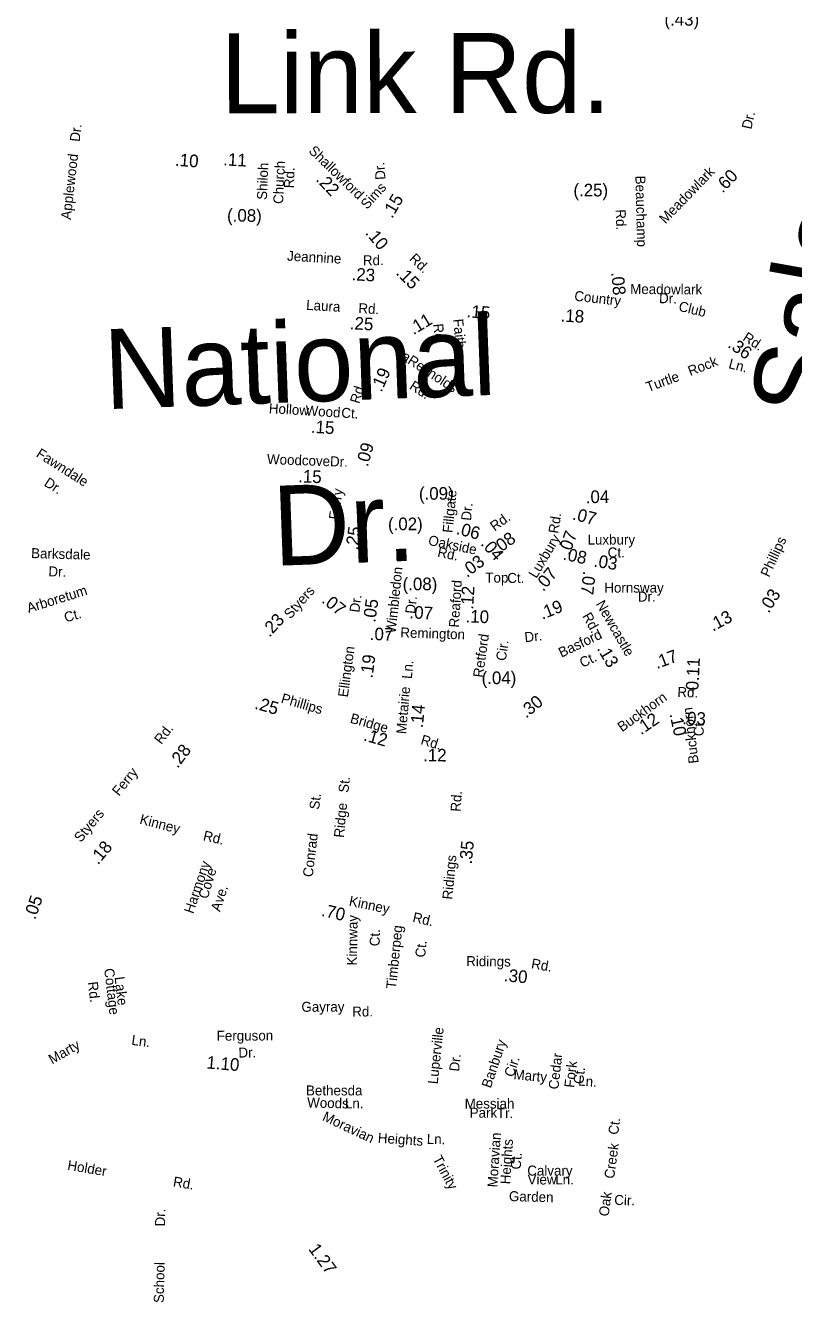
# Model space of a CAD drawing. Extents: x 1553981 to 1780076, y 812965 to 996873.
# Drawn here: x 1628137 to 1629049, y 846914 to 848432 of the extents above; entities that cross this region are included whole.
import ezdxf

# ---------------------------------------------------------------- set-up
doc = ezdxf.new("R2010")
doc.units = 0
for name, color, linetype in [('Exist Road Non-System Type 51 Label', 7, 'Continuous'), ('Exist Road Secondary Mileage Hundredths English Label', 7, 'Continuous'), ('Map Preparation Border Antique Large Shape', 7, 'Continuous')]:
    doc.layers.add(name, color=color, linetype=linetype)

msp = doc.modelspace()

# ---------------------------------------------------------------- texts
at = {"layer": 'Exist Road Non-System Type 51 Label'}
for s, height, rotation, p in [('Link', 95, 0.1507, (1628368.2, 848327.7)), ('Rd.', 95, 359.9684, (1628634.9, 848328.3)), ('Dr.', 11.88, 83.5506, (1628200.8, 848293.5)), ('Salem', 95, 79.854, (1629090.3, 847960.8)), ('Applewood', 11.88, 83.5506, (1628190.3, 848200.9)), ('National', 95, 2.1154, (1628231.3, 847975.9)), ('Rd.', 11.88, 275.4684, (1628621, 848077.2)), ('Faith', 11.88, 275.4684, (1628644.8, 848082.9)), ('La', 11.87, 327.0099, (1628574.9, 848040.7)), ('Reynolds', 11.87, 327.0099, (1628589.7, 848031.1)), ('Rock', 11.88, 21.3244, (1628926.7, 848015.2)), ('Ln.', 11.88, 345.6382, (1628971.5, 848024.9)), ('Rd.', 11.87, 327.0099, (1628591.9, 848000.8)), ('Turtle', 11.88, 19.9111, (1628876.6, 847996.3)), ('Fawndale', 11.88, 327.643, (1628148.2, 847920.2)), ('Dr.', 11.88, 327.643, (1628157.6, 847885.6)), ('Dr.', 95, 2.1154, (1628432, 847789.7)), ('Barksdale', 11.88, 358.3721, (1628143, 847799)), ('Dr.', 11.88, 358.4032, (1628163.6, 847777.3)), ('Arboretum', 11.87, 17.3636, (1628140.2, 847733.6)), ('Ct.', 11.88, 16.4615, (1628184.4, 847722.3)), ('Basford', 11.88, 25.6621, (1628773.6, 847680.4)), ('Ct.', 11.88, 25.6621, (1628798.6, 847668.4)), ('St.', 11.88, 84.1973, (1628520.2, 847519.5)), ('St.', 11.88, 83.0766, (1628485.5, 847499.5)), ('Ridge', 11.88, 84.1973, (1628514.8, 847466.1)), ('Conrad', 11.88, 83.0766, (1628477.8, 847419.2)), ('Harmony', 11.88, 71.4085, (1628335.8, 847375.4)), ('Cove', 11.88, 73.029, (1628352.9, 847392.9)), ('Ave.', 11.88, 71.7839, (1628367.6, 847377.8)), ('Kinnway', 11.88, 89.2551, (1628530.5, 847314.5)), ('Ct.', 11.88, 89.2551, (1628557.5, 847337.4)), ('Timberpeg', 11.88, 84.0792, (1628576.9, 847286.3)), ('Ct.', 11.88, 84.0792, (1628611.4, 847323.6)), ('Cottage', 11.88, 276.7917, (1628229.9, 847310.6)), ('Rd.', 11.88, 276.7917, (1628210.5, 847294.7)), ('Lake', 11.88, 276.7917, (1628242.3, 847300.7)), ('Gayray', 11.87, 0.2324, (1628464.5, 847259.5)), ('Rd.', 11.87, 0.2324, (1628524.9, 847253.9)), ('Ferguson', 11.88, 0.2987, (1628363.8, 847225.1)), ('Luperville', 11.87, 83.8524, (1628626.4, 847173.1)), ('Banbury', 11.88, 71.5075, (1628689.5, 847168)), ('Dr.', 11.88, 0.2944, (1628389.6, 847205.1)), ('Dr.', 11.87, 83.8524, (1628651.8, 847188.1)), ('Cir.', 11.88, 71.5075, (1628716.4, 847181)), ('Cedar', 11.88, 83.6288, (1628769.9, 847166.8)), ('Fork', 11.88, 83.6288, (1628788.7, 847168.8)), ('Ct.', 11.88, 83.6288, (1628799.5, 847173.1)), ('Bethesda', 11.88, 0.0147, (1628469.9, 847160.1)), ('Woods', 11.88, 358.6039, (1628471.2, 847145.8)), ('Ln.', 11.88, 0.3375, (1628516.2, 847144.7)), ('Moravian', 11.88, 334.7401, (1628488.4, 847130.9)), ('Ct.', 11.88, 82.1503, (1628840.8, 847112.8)), ('Heights', 11.88, 355.931, (1628555, 847103.9)), ('Ln.', 11.88, 358.9243, (1628613.4, 847102.5)), ('Moravian', 11.87, 86.2736, (1628697.4, 847050.5)), ('Heights', 11.87, 86.2736, (1628712.5, 847054.2)), ('Creek', 11.87, 82.1505, (1628836.1, 847060.6)), ('Trinity', 11.87, 298.3383, (1628620.1, 847084.8)), ('Ct.', 11.87, 86.2736, (1628725.1, 847071.7)), ('Garden', 11.88, 358.4068, (1628711, 847034.5)), ('Oak', 11.88, 82.5022, (1628829.6, 847015.8)), ('Cir.', 11.88, 358.4067, (1628836.2, 847030)), ('Dr.', 11.88, 89.1855, (1628302.3, 847004.3)), ('School', 11.88, 88.6092, (1628300.8, 846913.2))]:
    msp.add_text(s, height=height, rotation=rotation, dxfattribs=at).set_placement(p)
for s, p in [('Messiah', (1628658.5, 847144.5)), ('Park', (1628664.5, 847133.6)), ('Tr.', (1628696.9, 847133.1)), ('View', (1628733.3, 847054.2)), ('Calvary', (1628732.9, 847064.8)), ('Ln.', (1628766.2, 847054.2))]:
    msp.add_text(s, height=11.88, dxfattribs=at).set_placement(p)
at = {"layer": 'Exist Road Secondary Mileage Hundredths English Label'}
for s, rotation, p in [('(.43)', 359.8869, (1628896, 848432)), ('.11', 356.7836, (1628371.2, 848265.9)), ('.10', 355.4499, (1628313.8, 848265.5)), ('.22', 313.3313, (1628480.9, 848248.3)), ('.60', 46.2244, (1628965.1, 848232.2)), ('(.25)', 0.1572, (1628787.8, 848228.9)), ('.15', 59.7909, (1628572.3, 848202)), ('(.08)', 358.8738, (1628376, 848199.3)), ('.10', 310.3628, (1628539.6, 848185.1)), ('.23', 356.815, (1628523.8, 848129.3)), ('.15', 315.0435, (1628576.1, 848137)), ('.08', 275.1023, (1628832.7, 848138.6)), ('.15', 354.7302, (1628660.4, 848085.4)), ('.25', 356.6887, (1628521.7, 848071.1)), ('.11', 31.2732, (1628597.6, 848063.8)), ('.18', 356.8257, (1628772.3, 848080.2)), ('.36', 324.9959, (1628970.3, 848050.4)), ('.19', 66.2532, (1628559.7, 847995.4)), ('.15', 356.458, (1628475.4, 847948)), ('.09', 74.3042, (1628543.3, 847906.8)), ('.15', 357.9513, (1628460.4, 847889)), ('(.09)', 0.1363, (1628604.2, 847868.3)), ('.04', 0.9288, (1628802.6, 847864.2)), ('.07', 345.5918, (1628785.8, 847845)), ('(.02)', 0.077, (1628567.4, 847832.1)), ('.06', 345.5296, (1628647.6, 847827.7)), ('.25', 81.9383, (1628531.5, 847807.9)), ('.08', 36.1807, (1628698.1, 847802.7)), ('.07', 70.4784, (1628783.3, 847801.7)), ('.04', 310.9352, (1628676.8, 847815.5)), ('.08', 348.5323, (1628774.6, 847797.1)), ('.03', 37.0518, (1628661.3, 847775.2)), ('.03', 351.1126, (1628811.3, 847788.9)), ('.07', 50.503, (1628751.9, 847758.4)), ('.07', 263.3455, (1628799.6, 847784)), ('(.08)', 0.1363, (1628584.8, 847760.7)), ('.12', 86.3035, (1628668.5, 847737.5)), ('.07', 321.3265, (1628487.6, 847746.9)), ('.05', 81.984, (1628552.2, 847721.8)), ('.03', 57.9664, (1629019.9, 847732.6)), ('.07', 356.511, (1628592.6, 847727.5)), ('.10', 357.9747, (1628659.4, 847722.5)), ('.19', 22.1435, (1628750.8, 847725.5)), ('.13', 27.9174, (1628953.5, 847711.4)), ('.23', 47.6028, (1628426.5, 847704.1)), ('.07', 357.9154, (1628545.5, 847701.6)), ('.13', 300.4508, (1628815.3, 847691.3)), ('.17', 20.429, (1628887, 847666.9)), ('.19', 82.2999, (1628548.9, 847655.6)), ('0.11', 87.1393, (1628936.3, 847641.4)), ('(.04)', 0.077, (1628678.7, 847649.1)), ('.25', 343.863, (1628408, 847620.1)), ('.30', 39.7434, (1628731.6, 847607.9)), ('.14', 84.9183, (1628608.8, 847596.5)), ('.12', 34.5171, (1628868.1, 847588.1)), ('.03', 357.7644, (1628917.1, 847601.6)), ('.10', 282.105, (1628902, 847613.5)), ('.12', 344.1295, (1628537.4, 847582.3)), ('.28', 52.5224, (1628317.3, 847548.3)), ('.12', 359.5449, (1628609.1, 847557.3)), ('.18', 50.0939, (1628222.8, 847433.5)), ('.35', 84.4124, (1628666.9, 847434.5)), ('.05', 70.693, (1628148, 847368.3)), ('.70', 347.0316, (1628487.4, 847373.6)), ('.30', 354.345, (1628704.7, 847296)), ('1.10', 355.1763, (1628351.2, 847192.2)), ('1.27', 306.0462, (1628472.2, 846977.4))]:
    msp.add_text(s, height=15, rotation=rotation, dxfattribs=at).set_placement(p)
at = {"layer": 'Map Preparation Border Antique Large Shape'}
for s, height, rotation, p in [('Dr.', 11.88, 77.0361, (1628999.2, 848308.1)), ('Shallowford', 11.875, 315.9223, (1628472.2, 848282.1)), ('Shiloh', 11.88, 87.4428, (1628423.4, 848224.7)), ('Church', 11.88, 87.4428, (1628442.7, 848219.8)), ('Dr.', 11.88, 93.8335, (1628564.4, 848249.1)), ('Rd.', 11.88, 87.4428, (1628455.4, 848238.5)), ('Beauchamp', 11.88, 271.4581, (1628861.4, 848253.5)), ('Meadowlark', 11.88, 45.9332, (1628897.1, 848195.7)), ('Sims', 11.88, 47.5073, (1628542.5, 848212.8)), ('Rd.', 11.88, 271.4581, (1628838.1, 848213.4)), ('Jeannine', 11.88, 356.815, (1628447.2, 848152.6)), ('Rd.', 11.88, 0.6802, (1628537.6, 848147)), ('Rd.', 11.87, 316.4225, (1628591.9, 848153.8)), ('Country', 11.88, 353.5208, (1628788.4, 848105.1)), ('Meadowlark', 11.88, 359.5794, (1628855.2, 848113)), ('Dr.', 11.87, 358.624, (1628889.5, 848102.1)), ('Laura', 11.87, 356.6887, (1628469.9, 848094.1)), ('Rd.', 11.87, 356.7329, (1628531.9, 848090.3)), ('Club', 11.88, 346.4075, (1628912, 848093.1)), ('Rd.', 11.88, 326.7064, (1628988.1, 848058.5)), ('Rd.', 11.88, 72.8148, (1628533.2, 847981.8)), ('Hollow', 11.88, 356.458, (1628425.5, 847971.3)), ('Wood', 11.88, 356.458, (1628469.1, 847968.6)), ('Ct.', 11.88, 356.458, (1628511.6, 847966)), ('Woodcove', 11.87, 357.9513, (1628423.4, 847910.8)), ('Dr.', 11.87, 357.9513, (1628498.3, 847908.2)), ('Ferry', 11.88, 81.9101, (1628508.7, 847844)), ('Fillgate', 11.88, 84.3218, (1628644, 847828.5)), ('Dr.', 11.88, 84.3218, (1628666, 847843)), ('Rd.', 11.88, 35.7882, (1628694.1, 847830.4)), ('Rd.', 11.88, 81.2472, (1628769.7, 847827.6)), ('Oakside', 11.87, 348.2616, (1628614.5, 847814.8)), ('Luxbury', 11.88, 59.2168, (1628743.8, 847774.1)), ('Luxbury', 11.87, 0.0925, (1628804.6, 847815)), ('Rd.', 11.87, 348.2616, (1628625.5, 847800.8)), ('Phillips', 11.87, 65.2942, (1629020.4, 847775.4)), ('Wimbledon', 11.87, 83.9496, (1628576.4, 847709)), ('Styers', 11.88, 48.274, (1628451.3, 847725.8)), ('Reaford', 11.87, 86.3035, (1628651.6, 847716.1)), ('Dr.', 11.88, 81.984, (1628533.2, 847733.7)), ('Dr.', 11.87, 83.9496, (1628599.6, 847732.3)), ('Newcastle', 11.88, 299.8526, (1628814.1, 847744.5)), ('Rd.', 11.87, 299.2517, (1628797.9, 847730.1)), ('Remington', 11.88, 358.1725, (1628581.9, 847704.7)), ('Retford', 11.88, 81.9543, (1628680.2, 847656.4)), ('Dr.', 11.88, 6.6462, (1628730.3, 847698.8)), ('Ellington', 11.88, 82.2999, (1628519.6, 847633)), ('Cir.', 11.88, 81.9543, (1628707.4, 847676.2)), ('Ln.', 11.88, 84.9183, (1628595.7, 847654.9)), ('Metairie', 11.88, 84.9183, (1628588.8, 847589.4)), ('Rd.', 11.87, 357.7644, (1628911.2, 847634)), ('Phillips', 11.87, 343.863, (1628439.4, 847627.1)), ('Buckhorn', 11.88, 35.5762, (1628845.6, 847591.8)), ('Bridge', 11.88, 344.1295, (1628521.5, 847603.4)), ('Buckhorn', 11.88, 96.5427, (1628936.7, 847555.4)), ('Rd.', 11.87, 52.5224, (1628297.9, 847576.7)), ('Ct', 11.88, 89.0087, (1628942.6, 847587.1)), ('Rd.', 11.88, 343.3165, (1628605.4, 847577.9)), ('Ferry', 11.88, 50.8039, (1628247.5, 847515.2)), ('Rd.', 11.87, 85.844, (1628653.5, 847497.1)), ('Styers', 11.87, 50.4078, (1628202.2, 847460.1)), ('Kinney', 11.88, 345.4458, (1628271.4, 847483.3)), ('Rd.', 11.87, 347.0316, (1628346.9, 847463.6)), ('Ridings', 11.88, 84.4124, (1628643.7, 847392.6)), ('Kinney', 11.88, 348.2633, (1628520.3, 847385.8)), ('Rd.', 11.87, 347.0316, (1628595.9, 847366.6)), ('Ridings', 11.88, 359.398, (1628660.3, 847313.9)), ('Rd.', 11.87, 349.8743, (1628737, 847311.4)), ('Marty', 11.88, 29.9269, (1628168.1, 847196.8)), ('Ln.', 11.87, 352.7593, (1628262, 847220.3)), ('Marty', 11.87, 354.9033, (1628716.3, 847179.4)), ('Ln.', 11.88, 355.6368, (1628793.2, 847171.9)), ('Holder', 11.88, 350.4141, (1628185.7, 847071.7)), ('Rd.', 11.88, 350.4141, (1628311.3, 847052.1))]:
    msp.add_text(s, height=height, rotation=rotation, dxfattribs=at).set_placement(p)
for s, p in [('Ct.', (1628828.5, 847799.7)), ('Top', (1628683.1, 847769.8)), ('Ct.', (1628709.2, 847769.4)), ('Hornsway', (1628824.5, 847757.9)), ('Dr.', (1628864.4, 847747.2))]:
    msp.add_text(s, height=11.88, dxfattribs=at).set_placement(p)

doc.saveas('drawing.dxf')
